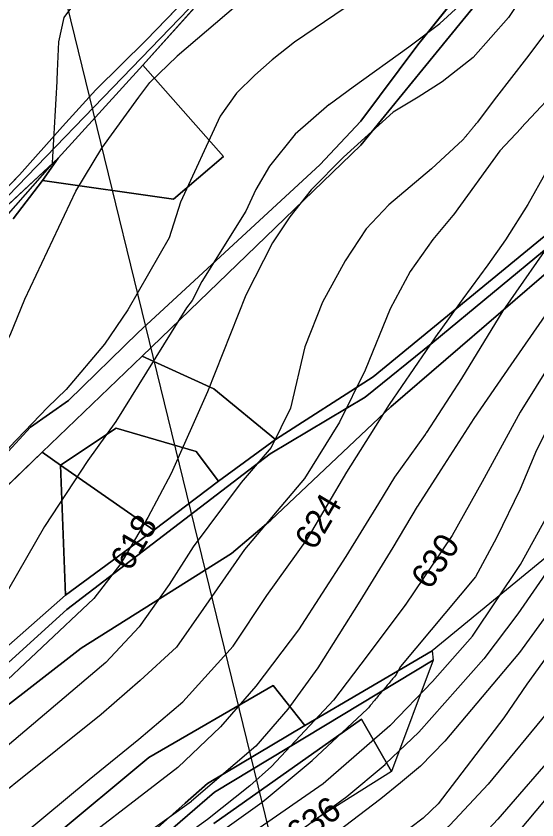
# Model space of a CAD drawing. Extents: x -709418 to -703832, y -1161719 to -1157826.
# Drawn here: x -706782.1 to -706614.7, y -1159816.4 to -1159557.8 of the extents above; entities that cross this region are included whole.
import ezdxf

# ---------------------------------------------------------------- set-up
doc = ezdxf.new("R2010")
doc.units = 0
for name, color, linetype in [('102_obvod PÚ', 7, 'Continuous'), ('106_zastavitelné plochy', 7, 'Continuous'), ('120_vrstevnice hlavní', 7, 'Continuous'), ('121_vrstevnice hlavní_popis', 7, 'Continuous'), ('122_vrstevnice základní', 7, 'Continuous'), ('201_orná půda_KN', 7, 'Continuous'), ('206_TTP_KN', 7, 'Continuous'), ('210_ostatní plocha_KN', 7, 'Continuous'), ('723_radioreléová trasa_UAP', 7, 'Continuous')]:
    doc.layers.add(name, color=color, linetype=linetype)

msp = doc.modelspace()

# ---------------------------------------------------------------- linework, layer by layer
at = {"layer": '102_obvod PÚ'}
msp.add_lwpolyline([(-706367.74, -1159673.93), (-706399.11, -1159654.57), (-706411.64, -1159613.17), (-706403.46, -1159603.15), (-706416.61, -1159600.76), (-706432.22, -1159605.07), (-706465.56, -1159597.19), (-706471.14, -1159590.54), (-706486.23, -1159597.28), (-706489.67, -1159605.09), (-706475.68, -1159616.83), (-706463.55, -1159617.01), (-706500.37, -1159633.07), (-706519.13, -1159645.05), (-706540.75, -1159658.99), (-706547.56, -1159651.15), (-706589.97, -1159678.86), (-706605.34, -1159693.95), (-706587.09, -1159711.95), (-706610.14, -1159730.65), (-706648.39, -1159762.04), (-706648.03, -1159765), (-706661.44, -1159800.87), (-706686.33, -1159816.5)], dxfattribs=at)
at = {"layer": '106_zastavitelné plochy'}
msp.add_lwpolyline([(-706699.08, -1159526.92), (-706830.66, -1159663.21), (-706893.51, -1159732.95), (-706913.28, -1159752.71), (-706948.73, -1159776.56), (-707000.54, -1159797.01), (-706999.86, -1159788.83), (-706998.55, -1159782.52), (-706991.13, -1159778.66), (-706993.63, -1159771.46), (-706950.95, -1159752.19), (-706963.59, -1159730.93), (-707001.32, -1159748.1), (-707016.41, -1159753.81), (-707020.99, -1159741.13), (-707003.27, -1159724.77), (-706948.05, -1159693.43), (-706937.82, -1159711.14), (-706958.96, -1159723.41), (-706952.14, -1159732.27), (-706932.37, -1159718.64), (-706922.06, -1159708.33)], dxfattribs=at)
at = {"layer": '120_vrstevnice hlavní'}
for points in [[(-706599.36, -1159545.61), (-706607.91, -1159557.89), (-706618.07, -1159571.37), (-706627.76, -1159583.84), (-706633.92, -1159592.08)], [(-706763.02, -1159553.25), (-706766.78, -1159558.34), (-706768.46, -1159566.12), (-706768.88, -1159575.57)], [(-706638.52, -1159597.69), (-706648.63, -1159606.97), (-706662.3, -1159618.54), (-706669.56, -1159626.26), (-706676.4, -1159636.55), (-706683.66, -1159649.84), (-706689.35, -1159664.23), (-706693.95, -1159683.94), (-706700.11, -1159696.65), (-706709.79, -1159707.92), (-706725.17, -1159728.56), (-706732.95, -1159740.7), (-706742.6, -1159754.29), (-706753.27, -1159765.73)], [(-706547.12, -1159602.7), (-706560.51, -1159613.3), (-706575.59, -1159626.97), (-706597.91, -1159652.48), (-706609.82, -1159668.71), (-706620.07, -1159685.26), (-706632.37, -1159707.7), (-706641.94, -1159724.9), (-706657.08, -1159747.29)], [(-706974.01, -1159913.97), (-706959.5, -1159902.65), (-706957.59, -1159896.67), (-706956.45, -1159887.7), (-706956.19, -1159861.76), (-706952.74, -1159850.24), (-706950.29, -1159844.74), (-706946.96, -1159839.25), (-706942.77, -1159833.75), (-706922.22, -1159811.18), (-706912.68, -1159799.47), (-706902.41, -1159788.76), (-706888.96, -1159776.61), (-706867.7, -1159755.35), (-706853.38, -1159737.27), (-706841.51, -1159718.03), (-706830.23, -1159696.05), (-706813.74, -1159668.85), (-706808.97, -1159658.44), (-706803.33, -1159642.67), (-706770.56, -1159605.48)], [(-706570.14, -1159708.76), (-706589.23, -1159732.95), (-706617.97, -1159772.72), (-706625.38, -1159783.55), (-706646.47, -1159811.2), (-706651.31, -1159815.9), (-706667.19, -1159827.83)], [(-706657.16, -1159747.4), (-706669.31, -1159763.69), (-706680.09, -1159777.92), (-706700.06, -1159799.23), (-706706.95, -1159805.45), (-706720.57, -1159816.24)], [(-706753.27, -1159765.73), (-706777.93, -1159786.73), (-706799.82, -1159805.13), (-706817.65, -1159820.01), (-706848.89, -1159847.78), (-706867.26, -1159866.15), (-706879.41, -1159881.48), (-706886.35, -1159893.34), (-706891.85, -1159904.62), (-706906.45, -1159940.48), (-706914.64, -1159958.98), (-706920.42, -1159968.23), (-706927.19, -1159976.29)], [(-706720.57, -1159816.24), (-706754.24, -1159840.65)]]:
    msp.add_lwpolyline(points, dxfattribs=at)
for points in [[(-706768.88, -1159575.58), (-706770.56, -1159605.48)], [(-706768.88, -1159575.57), (-706768.88, -1159575.58)], [(-706638.48, -1159597.64), (-706633.92, -1159592.08)], [(-706633.92, -1159592.08), (-706633.92, -1159592.08)], [(-706638.52, -1159597.69), (-706638.48, -1159597.64)], [(-706657.08, -1159747.29), (-706657.16, -1159747.4)]]:
    msp.add_open_spline(points, degree=1, dxfattribs=at)
at = {"layer": '122_vrstevnice základní'}
for points in [[(-706619.55, -1159445.89), (-706624.59, -1159454.52), (-706628.86, -1159465.05), (-706631.5, -1159477.96), (-706633.14, -1159491.38), (-706635.55, -1159502.75), (-706641.12, -1159516.75), (-706645.83, -1159525.04), (-706654.26, -1159536.18), (-706662.4, -1159544.04), (-706676.4, -1159555.18), (-706692.69, -1159566.19), (-706699.83, -1159571.9), (-706705.34, -1159576.79), (-706711.29, -1159582.62)], [(-706656.12, -1159449.89), (-706654.69, -1159462.75), (-706654.83, -1159471.9), (-706656.12, -1159481.04), (-706659.55, -1159492.47), (-706668.12, -1159509.61), (-706678.12, -1159524.04), (-706689.55, -1159537.18), (-706697.83, -1159544.61), (-706711.55, -1159554.61), (-706730.35, -1159570.68), (-706739.13, -1159579.22)], [(-706563.26, -1159531.12), (-706587.83, -1159558.83), (-706605.57, -1159578.52), (-706619.76, -1159593.82)], [(-706681.48, -1159586.27), (-706673.81, -1159580.61), (-706655.85, -1159567.77), (-706645.98, -1159560.2), (-706632.23, -1159547.56)], [(-706616.75, -1159547.57), (-706623.9, -1159558.29), (-706635.18, -1159571.18)], [(-706635.18, -1159571.18), (-706645.15, -1159578.94), (-706652.86, -1159583.9), (-706660.95, -1159588.78)], [(-706952.21, -1159904.95), (-706947.42, -1159896.51), (-706940.55, -1159881.92), (-706933.99, -1159865.49), (-706929.6, -1159854.58), (-706922.8, -1159840.69), (-706915.86, -1159831.43), (-706891.85, -1159809.01), (-706882.16, -1159798.74), (-706861.91, -1159773), (-706835.29, -1159741.32), (-706818.95, -1159719.77), (-706806.36, -1159700.68), (-706784.09, -1159660.47), (-706779.32, -1159648.89), (-706762.97, -1159614.18), (-706754.58, -1159600.29), (-706742.72, -1159583.95), (-706739.13, -1159579.22)], [(-706711.29, -1159582.62), (-706716.52, -1159590.02), (-706729.27, -1159617.65), (-706732.89, -1159629.22), (-706746.19, -1159652.36), (-706753.72, -1159663.36), (-706766.04, -1159678), (-706772.09, -1159683.75), (-706784.23, -1159696.48), (-706794.79, -1159709.21), (-706814.03, -1159741.03), (-706835.87, -1159772.28), (-706855.98, -1159798.89), (-706881.31, -1159828.32), (-706900.74, -1159847.56), (-706912.26, -1159860.91), (-706920.62, -1159874.81), (-706930.78, -1159890.2), (-706937.79, -1159902.61)], [(-706681.49, -1159586.27), (-706692.4, -1159595.86), (-706700.63, -1159606.08), (-706705.11, -1159613.6), (-706708.3, -1159620.54), (-706722.47, -1159643.25), (-706725.51, -1159649.33), (-706727.39, -1159651.64), (-706750.1, -1159688.24), (-706759.07, -1159700.82), (-706772.95, -1159722.08), (-706801.59, -1159771.7), (-706804.05, -1159776.9), (-706918.39, -1159887.65)], [(-706660.95, -1159588.78), (-706676.91, -1159603.19), (-706687.32, -1159613.74), (-706694.12, -1159622.42), (-706699.76, -1159630.81), (-706708.3, -1159647.59), (-706720.59, -1159678.69), (-706732.31, -1159705.02), (-706739.83, -1159719.19), (-706748.51, -1159733.94), (-706757.19, -1159745.23), (-706856.87, -1159839.1), (-706882.04, -1159862.88)], [(-706603.83, -1159595.77), (-706606.42, -1159599.69), (-706611.8, -1159607.89), (-706617.65, -1159618.43), (-706624.82, -1159629.82), (-706630.53, -1159637.86), (-706638.54, -1159648.76), (-706646.09, -1159659.46)], [(-706619.83, -1159593.89), (-706626.63, -1159601.15), (-706641.48, -1159621.72)], [(-706584.55, -1159598.12), (-706595.29, -1159608.85), (-706599.42, -1159614.83), (-706608.23, -1159627.56), (-706625.64, -1159652.63), (-706638.98, -1159674.38), (-706650.22, -1159691.76)], [(-706561.39, -1159600.96), (-706582.1, -1159618.78), (-706599.57, -1159636.08), (-706623.11, -1159670.05), (-706635.01, -1159687.29), (-706645.59, -1159703.84), (-706653.08, -1159715.45)], [(-706522.71, -1159605.69), (-706529.16, -1159608.45), (-706538.31, -1159613.27), (-706552.56, -1159623.1), (-706560.54, -1159629.37), (-706580.21, -1159647.04), (-706594.31, -1159662.43), (-706599.59, -1159669.27), (-706605.43, -1159678.68), (-706614.83, -1159697.49), (-706620.11, -1159710.03), (-706627.66, -1159725.7), (-706634.5, -1159738.24), (-706658.6, -1159767.11), (-706659.94, -1159769.66)], [(-706641.71, -1159622.03), (-706648.2, -1159629.69), (-706655.46, -1159639.98), (-706661.87, -1159651.98), (-706669.97, -1159671.75), (-706678.18, -1159688.49), (-706689.43, -1159706.58), (-706708.71, -1159729.47), (-706721.94, -1159748.41)], [(-706892.81, -1159962.06), (-706882.86, -1159946.78), (-706873.18, -1159931.12), (-706865.1, -1159915.53), (-706860.46, -1159904.12), (-706855.16, -1159893.55), (-706849.04, -1159883.65), (-706840.93, -1159873.62), (-706830.14, -1159862.79), (-706811.17, -1159847.63), (-706780.22, -1159821.28), (-706758.68, -1159803.4), (-706742.7, -1159790.44), (-706728.56, -1159778.47), (-706712.34, -1159760.5), (-706701.57, -1159744.25), (-706688.46, -1159725.96), (-706675.77, -1159704.54), (-706662.08, -1159682.75), (-706646.22, -1159659.65)], [(-706479.99, -1159688.87), (-706496.16, -1159690.14), (-706513.69, -1159694.76), (-706529.22, -1159703.78), (-706537.46, -1159709.46), (-706552.85, -1159723.7), (-706566.67, -1159738.81), (-706583.77, -1159760.04), (-706607, -1159792.81), (-706627.23, -1159816.18), (-706636.21, -1159825.73), (-706646.31, -1159834.43), (-706656.76, -1159841.61), (-706669.98, -1159850.17)], [(-706650.66, -1159692.43), (-706660.45, -1159706.17), (-706665.61, -1159714.65), (-706676.19, -1159731.72), (-706691.34, -1159755.31), (-706705.07, -1159773.41), (-706716.39, -1159786.43), (-706730.17, -1159799.55), (-706770.72, -1159830.91), (-706789.82, -1159844.1), (-706814.32, -1159865.65), (-706827.19, -1159878.59), (-706833.7, -1159887.12), (-706843.68, -1159904.48), (-706859.29, -1159932.03), (-706872.34, -1159951.47)], [(-706540.39, -1159698.57), (-706554.65, -1159711.42), (-706570.05, -1159726.83), (-706581.06, -1159737.95), (-706609.7, -1159779.85), (-706630.37, -1159804.93), (-706642.72, -1159818.11), (-706652.19, -1159826.59), (-706668.36, -1159837.21)], [(-706661.86, -1159786.05), (-706648.29, -1159771.94), (-706635.39, -1159757.32), (-706619.96, -1159734.25), (-706602.49, -1159702.51)], [(-706620.53, -1159820.17), (-706612.13, -1159810.2), (-706583.34, -1159773.29), (-706567.24, -1159754.91), (-706552.56, -1159740.66), (-706531.05, -1159723.56), (-706515.09, -1159713.59), (-706496.99, -1159705.32), (-706487.42, -1159702.71), (-706468.49, -1159703.9), (-706450.25, -1159708.74), (-706445.69, -1159710.74), (-706440.14, -1159714.44), (-706430.59, -1159723.99), (-706422.32, -1159733.54), (-706414.63, -1159743.94), (-706404.09, -1159759.9), (-706395.11, -1159775.86), (-706387.41, -1159794.1), (-706382.85, -1159807.78), (-706377.58, -1159830.57)], [(-706653.2, -1159715.65), (-706661.05, -1159728.82), (-706671.62, -1159746.04), (-706685.13, -1159767.45), (-706694.75, -1159780.84), (-706705.06, -1159792.75), (-706725.76, -1159810.42)], [(-706609.84, -1159734.13), (-706620.89, -1159750.1), (-706631.76, -1159764.56), (-706652.72, -1159788.19), (-706663.4, -1159798.43)], [(-706603.97, -1159739.91), (-706620.27, -1159762.59), (-706644.33, -1159791.1), (-706652.17, -1159799.08), (-706658.58, -1159804.5), (-706664.92, -1159809.65)], [(-706721.94, -1159748.41), (-706730.6, -1159760.82), (-706742.26, -1159771.6), (-706754.76, -1159782.56), (-706811.57, -1159828.03), (-706847.73, -1159861.09), (-706860.96, -1159878.05), (-706870.48, -1159893.22), (-706876.33, -1159907.78), (-706883.32, -1159925.2), (-706890.86, -1159941.57), (-706899.72, -1159957.09)], [(-706901.94, -1160034.93), (-706878.5, -1160015.52), (-706849.61, -1159986.78), (-706841.37, -1159975.5), (-706821.11, -1159939.85), (-706807.38, -1159911.34), (-706797.19, -1159894.26), (-706784.64, -1159877.2), (-706766.31, -1159858.07), (-706742.37, -1159838.77), (-706703.06, -1159810.72), (-706686.98, -1159797.26), (-706669.15, -1159780.66)], [(-706661.99, -1159786.17), (-706683.4, -1159804.81), (-706723.19, -1159832.42), (-706744.52, -1159849.25), (-706769.77, -1159871.5), (-706778.88, -1159882.2), (-706787.27, -1159893.92), (-706795.37, -1159907.52), (-706806.65, -1159930.95), (-706831.53, -1159975.5), (-706839.2, -1159986.93), (-706849.9, -1159999.37), (-706851.78, -1160002.55), (-706882.16, -1160027.72)], [(-706836.28, -1160005.21), (-706833.85, -1159994.16), (-706822.42, -1159977.24), (-706813.45, -1159962.48), (-706793.49, -1159924.87), (-706791.9, -1159921.84), (-706782.65, -1159906.17), (-706771.22, -1159890.16), (-706757.47, -1159872.95), (-706745.33, -1159860.51), (-706733.18, -1159849.8), (-706722.04, -1159841.12), (-706703.81, -1159828.83), (-706688.1, -1159817.93), (-706675.8, -1159808.84), (-706663.54, -1159798.55)], [(-706848.67, -1159942.59), (-706839.9, -1159927.05), (-706831.63, -1159911.52), (-706822.83, -1159894.4), (-706816.99, -1159883.99), (-706811.86, -1159878.15), (-706799.71, -1159864.99), (-706780.04, -1159848.94), (-706776.28, -1159846.62), (-706725.76, -1159810.42)], [(-706664.92, -1159809.65), (-706676.56, -1159818.59), (-706701.5, -1159837.65), (-706715.38, -1159846.91), (-706730.72, -1159858.77), (-706745.33, -1159872.95), (-706758.2, -1159886.98), (-706770.35, -1159902.31), (-706779.46, -1159917.35), (-706788.72, -1159934.42), (-706814.03, -1159978.1), (-706818.08, -1159984.03), (-706819.82, -1159995.6)]]:
    msp.add_lwpolyline(points, dxfattribs=at)
for points in [[(-706635.18, -1159571.18), (-706635.18, -1159571.18)], [(-706739.13, -1159579.22), (-706739.13, -1159579.22)], [(-706711.29, -1159582.62), (-706711.29, -1159582.62)], [(-706681.48, -1159586.27), (-706681.49, -1159586.27)], [(-706660.95, -1159588.78), (-706660.95, -1159588.78)], [(-706619.76, -1159593.82), (-706619.83, -1159593.89)], [(-706641.48, -1159621.72), (-706641.71, -1159622.03)], [(-706646.22, -1159659.65), (-706646.09, -1159659.46)], [(-706650.22, -1159691.76), (-706650.66, -1159692.43)], [(-706653.08, -1159715.45), (-706653.2, -1159715.65)], [(-706659.94, -1159769.66), (-706669.15, -1159780.66)], [(-706659.94, -1159769.66), (-706659.94, -1159769.66)], [(-706661.86, -1159786.05), (-706661.99, -1159786.17)], [(-706663.54, -1159798.55), (-706663.4, -1159798.43)], [(-706664.92, -1159809.65), (-706664.92, -1159809.65)]]:
    msp.add_open_spline(points, degree=1, dxfattribs=at)
at = {"layer": '201_orná půda_KN'}
for p, q in [((-706877.13, -1159796.96), (-706773.77, -1159698.16)), ((-706773.77, -1159698.16), (-706767.88, -1159702.26)), ((-706767.88, -1159702.26), (-706766.24, -1159744.08)), ((-706766.24, -1159744.08), (-706789.95, -1159764.97))]:
    msp.add_line(p, q, dxfattribs=at)
for points in [[(-706352.85, -1159517.15), (-706391.81, -1159525.36), (-706421.49, -1159531.99), (-706450.7, -1159537.9), (-706523.06, -1159572.25), (-706542.97, -1159576.56), (-706593.1, -1159617.45), (-706606.85, -1159614.86), (-706610.6, -1159627.21), (-706667.35, -1159673.86), (-706698.79, -1159694.01), (-706718.6, -1159677.79), (-706741.65, -1159667.26)], [(-706741.65, -1159667.26), (-706671.31, -1159599.34), (-706651.4, -1159574.94), (-706638.56, -1159559.13), (-706609, -1159522.95)]]:
    msp.add_lwpolyline(points, dxfattribs=at)
at = {"layer": '206_TTP_KN'}
for p, q in [((-706623, -1159529.64), (-706652.97, -1159567.04)), ((-706741.39, -1159573.66), (-706718.93, -1159548.48)), ((-706652.97, -1159567.04), (-706671.31, -1159591.66)), ((-706715.46, -1159603.04), (-706741.39, -1159573.66)), ((-706671.31, -1159591.66), (-706684.51, -1159605.64)), ((-706731.56, -1159616.74), (-706715.46, -1159603.04)), ((-706684.51, -1159605.64), (-706742.94, -1159659.59)), ((-706783.1, -1159623.07), (-706773.64, -1159610.72)), ((-706773.64, -1159610.72), (-706731.56, -1159616.74)), ((-706661.7, -1159683.54), (-706603.96, -1159633.83)), ((-706742.94, -1159659.59), (-706765.29, -1159681.52)), ((-706773.77, -1159698.16), (-706741.65, -1159667.26)), ((-706741.65, -1159667.26), (-706718.6, -1159677.79)), ((-706718.6, -1159677.79), (-706698.79, -1159694.01)), ((-706765.29, -1159681.52), (-706777.45, -1159690.03)), ((-706700.24, -1159720), (-706661.7, -1159683.54)), ((-706777.45, -1159690.03), (-706827.14, -1159743.87)), ((-706749.93, -1159690.42), (-706767.88, -1159702.26)), ((-706724.24, -1159697.95), (-706749.93, -1159690.42)), ((-706698.79, -1159694.01), (-706717.03, -1159707.4)), ((-706767.88, -1159702.26), (-706773.77, -1159698.16)), ((-706717.03, -1159707.4), (-706724.24, -1159697.95)), ((-706767.88, -1159702.26), (-706737.87, -1159723.17)), ((-706766.24, -1159744.08), (-706767.88, -1159702.26)), ((-706712.87, -1159730.71), (-706700.24, -1159720)), ((-706737.87, -1159723.17), (-706766.24, -1159744.08)), ((-706761.18, -1159761.18), (-706712.87, -1159730.71)), ((-706610.14, -1159730.65), (-706648.39, -1159762.04)), ((-706790.82, -1159784.11), (-706761.18, -1159761.18)), ((-706648.39, -1159762.04), (-706689.34, -1159786.1)), ((-706739.51, -1159796.39), (-706699.48, -1159773.19)), ((-706699.48, -1159773.19), (-706739.51, -1159796.39)), ((-706699.48, -1159773.19), (-706689.34, -1159786.1)), ((-706689.34, -1159786.1), (-706699.48, -1159773.19)), ((-706718.6, -1159817.57), (-706671.14, -1159784.03)), ((-706671.14, -1159784.03), (-706661.44, -1159800.87)), ((-706689.34, -1159786.1), (-706720.6, -1159804.68)), ((-706781.97, -1159831.71), (-706739.51, -1159796.39)), ((-706739.51, -1159796.39), (-706781.97, -1159831.71)), ((-706661.44, -1159800.87), (-706686.33, -1159816.5)), ((-706720.6, -1159804.68), (-706727.84, -1159811.03)), ((-706727.84, -1159811.03), (-706764.08, -1159843.37))]:
    msp.add_line(p, q, dxfattribs=at)
msp.add_lwpolyline([(-706721.06, -1159545.49), (-706740.27, -1159565.63), (-706756.5, -1159581.55), (-706767.24, -1159593.33), (-706781.02, -1159608.89), (-706790.51, -1159618.63), (-706810.49, -1159637.54), (-706816.48, -1159644.1), (-706830.18, -1159659.38), (-706841.14, -1159670.97), (-706856.43, -1159688.73), (-706884.45, -1159711.66), (-706881.99, -1159714.76), (-706928.31, -1159751.83), (-706947.58, -1159727.78), (-706955.37, -1159734.01), (-706953.1, -1159741.94), (-706941.64, -1159737.83), (-706937.01, -1159750), (-706948.87, -1159756.5), (-706991.13, -1159778.66), (-706993.63, -1159771.46)], dxfattribs=at)
at = {"layer": '210_ostatní plocha_KN'}
for p, q in [((-706609, -1159522.95), (-706638.56, -1159559.13)), ((-706652.97, -1159567.04), (-706623, -1159529.64)), ((-706740.27, -1159565.63), (-706721.06, -1159545.49)), ((-706718.93, -1159548.48), (-706741.39, -1159573.66)), ((-706638.56, -1159559.13), (-706651.4, -1159574.94)), ((-706756.5, -1159581.55), (-706740.27, -1159565.63)), ((-706671.31, -1159591.66), (-706652.97, -1159567.04)), ((-706741.39, -1159573.66), (-706768.64, -1159603.54)), ((-706768.64, -1159603.54), (-706741.39, -1159573.66)), ((-706741.39, -1159573.66), (-706715.46, -1159603.04)), ((-706651.4, -1159574.94), (-706671.31, -1159599.34)), ((-706767.24, -1159593.33), (-706756.5, -1159581.55)), ((-706781.02, -1159608.89), (-706767.24, -1159593.33)), ((-706684.51, -1159605.64), (-706671.31, -1159591.66)), ((-706671.31, -1159599.34), (-706741.65, -1159667.26)), ((-706768.64, -1159603.54), (-706793.75, -1159626.94)), ((-706773.64, -1159610.72), (-706768.64, -1159603.54)), ((-706715.46, -1159603.04), (-706731.56, -1159616.74)), ((-706742.94, -1159659.59), (-706684.51, -1159605.64)), ((-706790.51, -1159618.63), (-706781.02, -1159608.89)), ((-706731.56, -1159616.74), (-706773.64, -1159610.72)), ((-706667.35, -1159673.86), (-706610.6, -1159627.21)), ((-706609.83, -1159631.09), (-706648.22, -1159662.85)), ((-706648.22, -1159662.85), (-706609.83, -1159631.09)), ((-706603.96, -1159633.83), (-706661.7, -1159683.54)), ((-706765.29, -1159681.52), (-706742.94, -1159659.59)), ((-706648.22, -1159662.85), (-706669.98, -1159680.47)), ((-706669.98, -1159680.47), (-706648.22, -1159662.85)), ((-706741.65, -1159667.26), (-706773.77, -1159698.16)), ((-706698.79, -1159694.01), (-706667.35, -1159673.86)), ((-706777.45, -1159690.03), (-706765.29, -1159681.52)), ((-706669.98, -1159680.47), (-706700.45, -1159698.67)), ((-706700.45, -1159698.67), (-706669.98, -1159680.47)), ((-706661.7, -1159683.54), (-706700.24, -1159720)), ((-706827.14, -1159743.87), (-706777.45, -1159690.03)), ((-706767.88, -1159702.26), (-706749.93, -1159690.42)), ((-706749.93, -1159690.42), (-706724.24, -1159697.95)), ((-706717.03, -1159707.4), (-706698.79, -1159694.01)), ((-706773.77, -1159698.16), (-706877.13, -1159796.96)), ((-706700.45, -1159698.67), (-706765.82, -1159748.69)), ((-706765.82, -1159748.69), (-706700.45, -1159698.67)), ((-706724.24, -1159697.95), (-706717.03, -1159707.4)), ((-706737.87, -1159723.17), (-706767.88, -1159702.26)), ((-706737.87, -1159723.17), (-706717.03, -1159707.4)), ((-706717.03, -1159707.4), (-706737.87, -1159723.17)), ((-706700.24, -1159720), (-706712.87, -1159730.71)), ((-706766.24, -1159744.08), (-706737.87, -1159723.17)), ((-706712.87, -1159730.71), (-706761.18, -1159761.18)), ((-706789.95, -1159764.97), (-706766.24, -1159744.08)), ((-706765.82, -1159748.69), (-706789.63, -1159770.3)), ((-706789.63, -1159770.3), (-706765.82, -1159748.69)), ((-706761.18, -1159761.18), (-706790.82, -1159784.11)), ((-706689.34, -1159786.1), (-706648.39, -1159762.04)), ((-706648.39, -1159762.04), (-706648.03, -1159765)), ((-706718.32, -1159807.46), (-706648.03, -1159765)), ((-706648.03, -1159765), (-706718.32, -1159807.46)), ((-706648.03, -1159765), (-706661.44, -1159800.87)), ((-706671.14, -1159784.03), (-706718.6, -1159817.57)), ((-706661.44, -1159800.87), (-706671.14, -1159784.03)), ((-706720.6, -1159804.68), (-706689.34, -1159786.1)), ((-706727.84, -1159811.03), (-706720.6, -1159804.68)), ((-706757.28, -1159841.07), (-706718.32, -1159807.46)), ((-706718.32, -1159807.46), (-706757.28, -1159841.07)), ((-706764.08, -1159843.37), (-706727.84, -1159811.03))]:
    msp.add_line(p, q, dxfattribs=at)
msp.add_lwpolyline([(-706793.75, -1159626.94), (-706768.64, -1159603.54), (-706773.64, -1159610.72), (-706783.1, -1159623.07)], dxfattribs=at)
at = {"layer": '723_radioreléová trasa_UAP'}
msp.add_lwpolyline([(-707182.2, -1157850.62), (-706271.36, -1161577.76)], dxfattribs=at)

# ---------------------------------------------------------------- texts
at = {"layer": '121_vrstevnice hlavní_popis'}
for s, rotation, p in [('624', 59.4398, (-706686.18, -1159730.04)), ('618', 59.7087, (-706745.44, -1159736.79)), ('630', 55.8845, (-706649.13, -1159742.71)), ('636', 35.7996, (-706691.47, -1159825.23))]:
    msp.add_text(s, height=8, rotation=rotation, dxfattribs=at).set_placement(p)

doc.saveas('drawing.dxf')
